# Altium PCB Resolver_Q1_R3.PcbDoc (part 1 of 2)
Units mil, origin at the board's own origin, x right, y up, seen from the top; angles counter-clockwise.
Board outline 2524 x 1600 mil, 2 copper layers (Top Layer, Bottom Layer), stack 62 mil thick; 100 components, 53 nets, 290 pads, 103 vias.
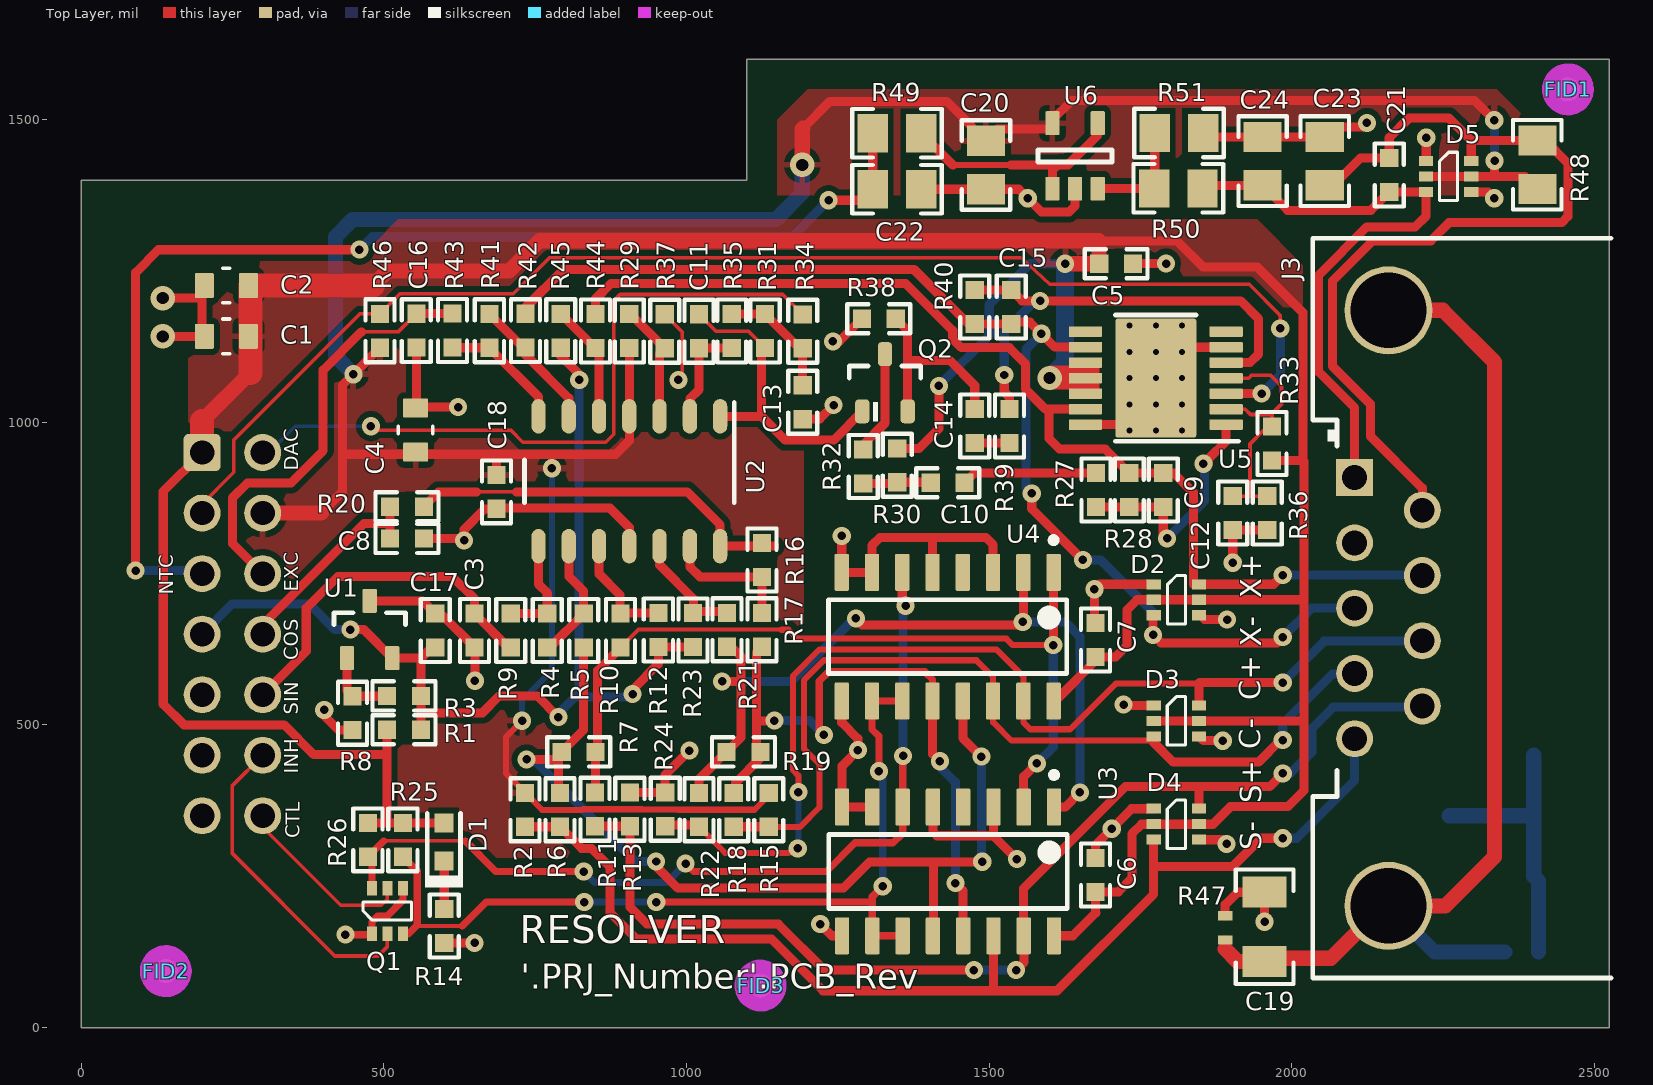
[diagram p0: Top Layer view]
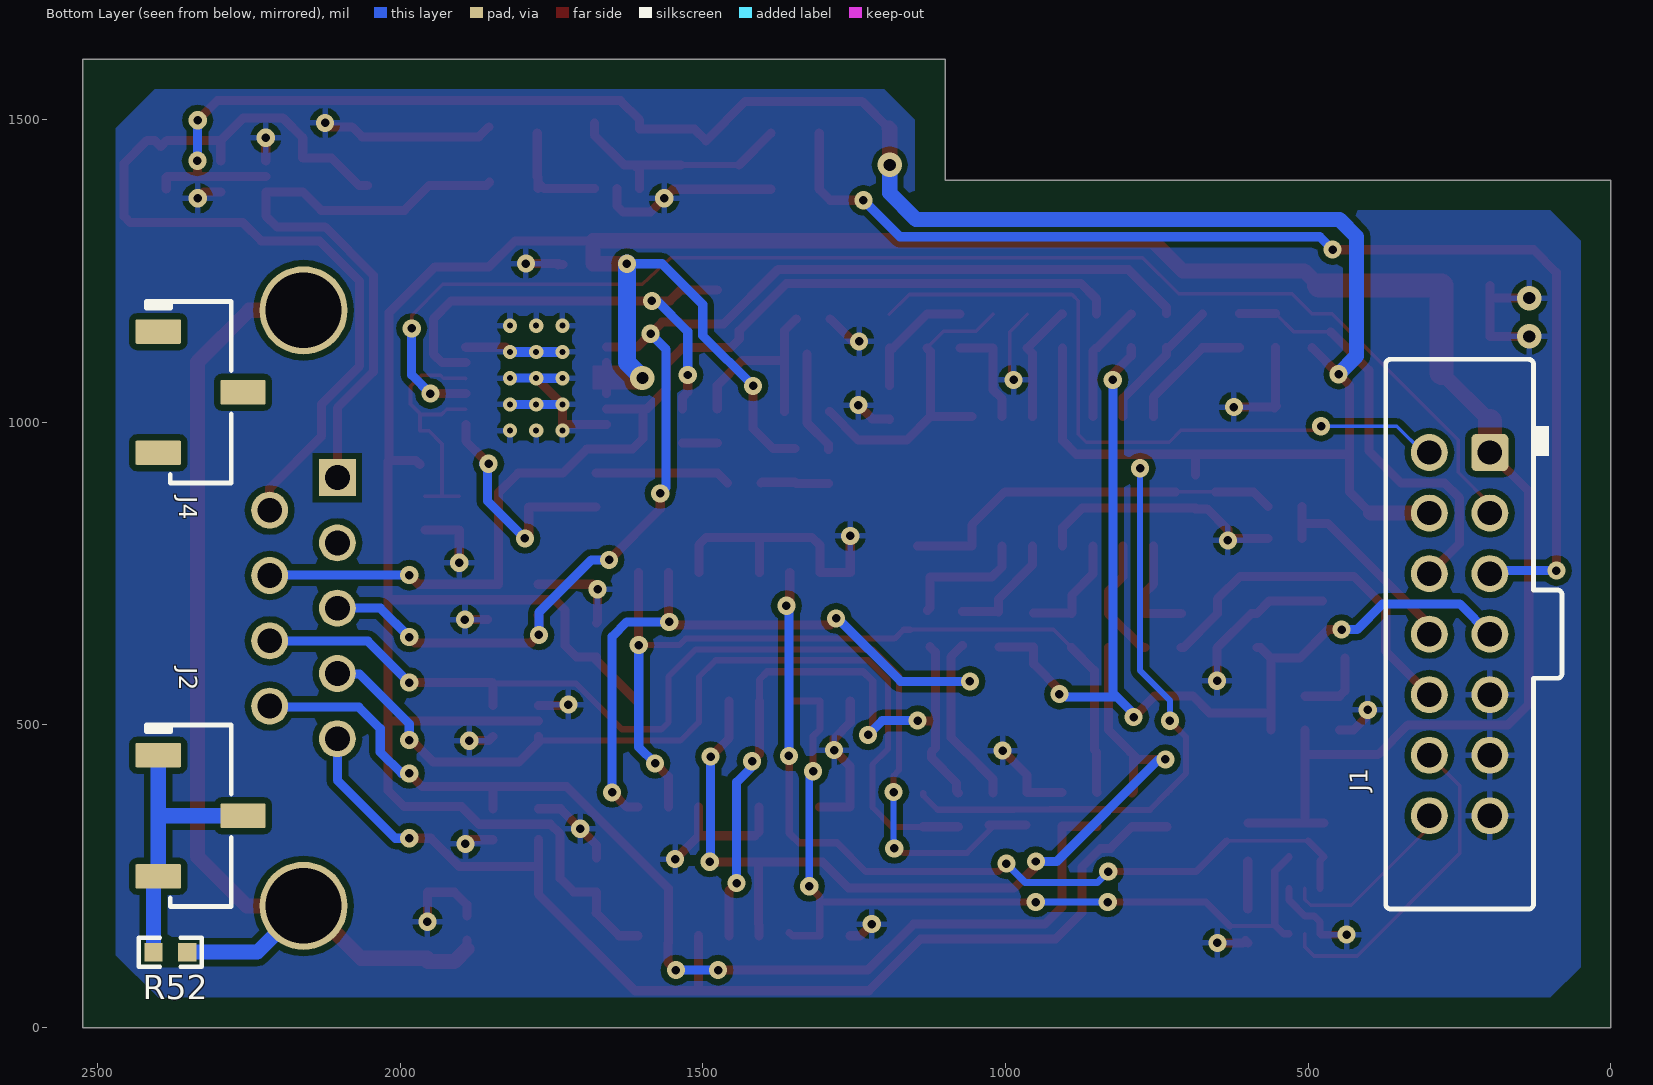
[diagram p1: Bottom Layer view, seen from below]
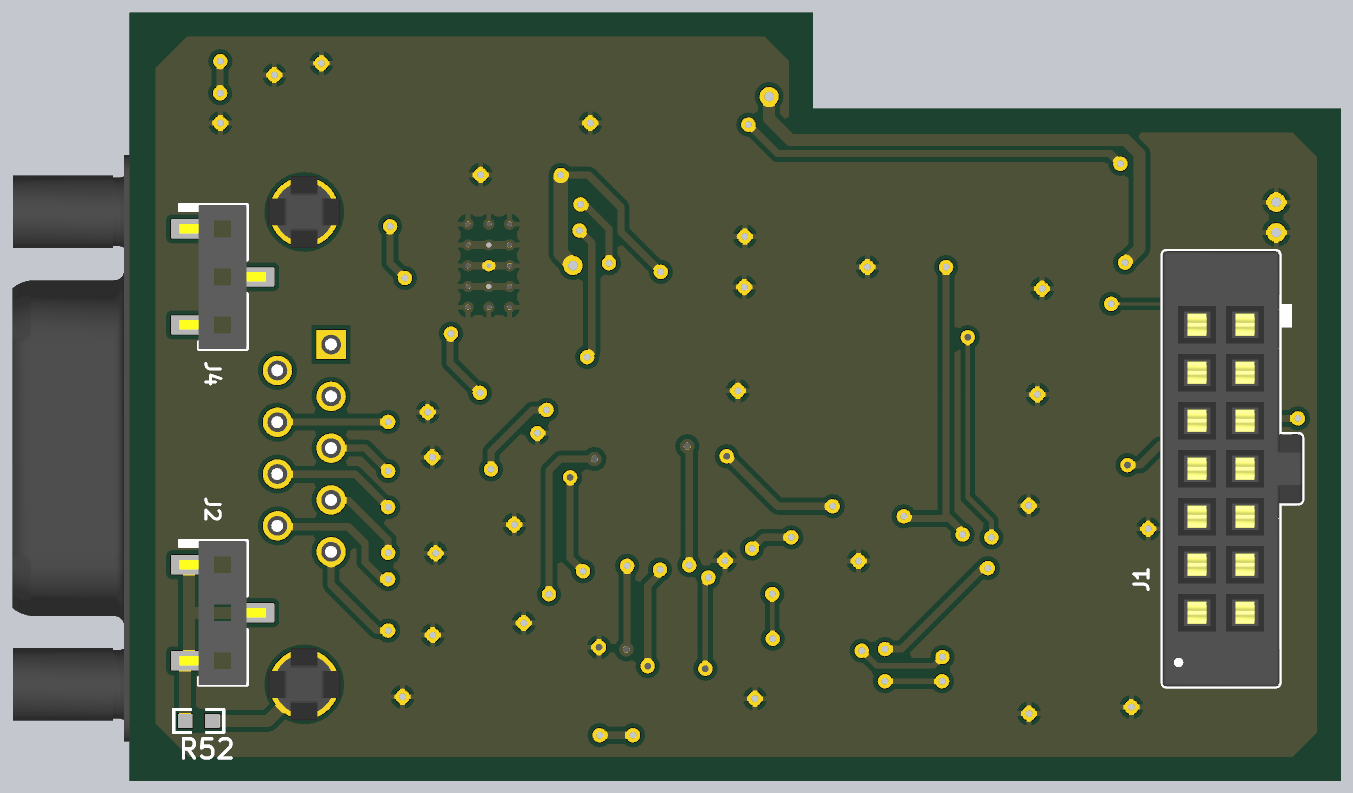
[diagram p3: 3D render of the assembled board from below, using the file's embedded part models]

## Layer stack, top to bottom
Top Solder: solder mask 0.4, Solder Resist, Dk 3.5
Top Layer: signal copper 1.4
Dielectric1: core 59.2, FR-4, Dk 4.8
Bottom Layer: signal copper 1.4
Bottom Solder: solder mask 0.4, Solder Resist, Dk 3.5

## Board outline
0,0 0,1400 1100,1400 1100,1600 2524,1600 2524,0

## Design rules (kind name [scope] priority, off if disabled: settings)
AcuteAngle [All] p1: minimum=4.50000000000000E+0001 checktracksonly=FALSE
AssemblyTestPointUsage [All] p1: valid=2
BoardOutlineClearance BoardOutlineClearance_MountingHoles [OnCopper and InComponentClass('Mounting Holes')] p1: gap=39.37 ignorepadtopadclearanceinfootprint=FALSE
BoardOutlineClearance BoardOutlineClearance_Poly [OnCopper and IsPoly] p2: gap=25 ignorepadtopadclearanceinfootprint=FALSE
BoardOutlineClearance [OnCopper and Not InComponentClass('Logo') and not InComponentClass('FiducialMark') and not InRegion(1000,500,4000,800) and not InPoly] p3: gap=50 ignorepadtopadclearanceinfootprint=FALSE
Clearance Clearance_Keepouts [((IsTrack Or IsArc) And Not InPoly) And IsFree and IsKeepOut vs ((IsTrack Or IsArc) And Not InPoly) And IsFree and IsKeepOut] p1: gap=0 ignorepadtopadclearanceinfootprint=FALSE
Clearance Clearance_Poly [InPolygon] p2: gap=10 ignorepadtopadclearanceinfootprint=TRUE
Clearance Clearance_FiducialMark [IsKeepOut and InComponentClass('FiducialMark') vs IsPad and InComponentClass('FiducialMark')] p3: gap=0 ignorepadtopadclearanceinfootprint=FALSE
Clearance [All] p4: gap=7.87 ignorepadtopadclearanceinfootprint=TRUE
ComponentClearance ComponentClearance_MountingHoles_FiducialMarks [InComponentClass('Mounting Holes') vs InComponentClass('FiducialMark')] p1: gap=50 collisioncheckmode=3 verticalgap=10 showdistances=FALSE
ComponentClearance ComponentClearance_Shunt [InComponentClass('Header') vs InComponentClass('Shunt')] p2: gap=0 collisioncheckmode=3 verticalgap=0 showdistances=FALSE
ComponentClearance ComponentClearance_Logo [InComponentClass('Logo')] p3: gap=20 collisioncheckmode=3 verticalgap=10 showdistances=FALSE
ComponentClearance ComponentClearance_ScrewToNut [(HasFootprint('NY PMS 440 0025 PH')) vs (HasFootprint('Keystone_1902C'))] p4: gap=5 collisioncheckmode=3 verticalgap=10 showdistances=FALSE
ComponentClearance ComponentClearance_MountingHoles [InComponentClass('Mounting Holes')] p5: gap=250 collisioncheckmode=3 verticalgap=100000 showdistances=FALSE
ComponentClearance ComponentClearance_SmallPassives [HasFootprint('0201*') or HasFootprint('0402*') or HasFootprint('0508') or HasFootprint('0603*') or HasFootprint('0612') or HasFootprint('0805*') or HasFootprint('0815*') or HasFootprint('0830*') or HasFootprint('1206*') or HasFootprint('1210*') or HasFootprint('1808*') or HasFootprint('1812*') or HasFootprint('1825*') or HasFootprint('2010*') or HasFootprint('2220*') or HasFootprint('2225*') or HasFootprint('2512*') or HasFootprint('2728*') or HasFootprint('3518*') vs HasFootprint('0201*') or HasFootprint('0402*') or HasFootprint('0508') or HasFootprint('0603*') or HasFootprint('0612') or HasFootprint('0805*') or HasFootprint('0815*') or HasFootprint('0830*') or HasFootprint('1206*') or HasFootprint('1210*') or HasFootprint('1808*') or HasFootprint('1812*') or HasFootprint('1825*') or HasFootprint('2010*') or HasFootprint('2220*') or HasFootprint('2225*') or HasFootprint('2512*') or HasFootprint('2728*') or HasFootprint('3518*')] p6: gap=14.96 collisioncheckmode=3 verticalgap=10 showdistances=FALSE
ComponentClearance ComponentClearance_THtoSMT [IsThruComponent vs IsSMTComponent] p7: gap=40 collisioncheckmode=3 verticalgap=30 showdistances=FALSE
ComponentClearance ComponentClearance_THtoTH [IsThruComponent vs IsThruComponent] p8: gap=30 collisioncheckmode=3 verticalgap=30 showdistances=FALSE
ComponentClearance [All] p9: gap=30 collisioncheckmode=3 verticalgap=10 showdistances=FALSE
DiffPairsRouting [All] p1: maxlimit=100 minlimit=10 mostfreqgap=10 toplayer_minwidth=15 toplayer_maxwidth=15 toplayer_prefwidth=15 bottomlayer_minwidth=15 bottomlayer_maxwidth=15 bottomlayer_prefwidth=15 maxuncoupledlength=1000
FabricationTestPointUsage TestPointUsage [All] p1: valid=2 allowmultiple=FALSE
FabricationTestpoint Testpoint [All] p1: side=3 testpointundercomponent=TRUE minsize=40 maxsize=100 preferedsize=60 minholesize=0 maxholesize=40 preferedholesize=32 testpointgrid=1 allowsidetop=TRUE allowsidebottom=TRUE usegrid=TRUE gridtolerance=0.01
FanoutControl Fanout_LCC [IsLCC] p1: bgadir=Out bgaviamode=Centered fanoutstyle=Auto fanoutdirection=Alternating viagrid=1 // Fanout_LCC (Default Rule)
FanoutControl Fanout_BGA [IsBGA] p2: bgadir=Out bgaviamode=Centered fanoutstyle=Auto fanoutdirection=Alternating viagrid=1 // Fanout_BGA (Default Rule)
FanoutControl Fanout_Default [All] p4: bgadir=Out bgaviamode=Centered fanoutstyle=Auto fanoutdirection=Alternating viagrid=1 // Fanout_Default (Default Rule)
FanoutControl Fanout_Small [(CompPinCount < 5)] p5: bgadir=Out bgaviamode=Centered fanoutstyle=Auto fanoutdirection=OutThenIn viagrid=1 // Fanout_Small (Default Rule)
HoleSize [All] p1: absolutevalues=TRUE maxlimit=251 minlimit=7.87 maxpercent=80.000 minpercent=20.000
MinimumAnnularRing MinimumAnnularRing_ThermalPadVias [IsVia and InAnyComponent] p1: minimumring=5.91
MinimumAnnularRing [All] p2: minimumring=7.87
MinimumSolderMaskSliver MinimumSolderMaskSliver_Logo [InComponentClass('Logo') vs InComponentClass('Logo')] p1: minsoldermaskwidth=0.7
MinimumSolderMaskSliver [All] p2: minsoldermaskwidth=3.94
PlaneConnect [All] p1: planeconnectstyle=Relief reliefexpansion=10 reliefentries=4 reliefconductorwidth=10 reliefairgap=10
PolygonConnect [All] p1: connectstyle=Relief reliefconductorwidth=10 reliefentries=4 polygonreliefangle="90 Angle" airgapwidth=10
RoutingVias ThermalPadVias [IsVia and InAnyComponent] p1: holewidth=7.87 width=19.68 viastyle="Through Hole" minholewidth=7.87 minwidth=19.68 maxholewidth=12.99 maxwidth=23.62
RoutingVias [All] p2: holewidth=16 width=34 viastyle="Through Hole" minholewidth=7.87 minwidth=26 maxholewidth=40 maxwidth=65
SilkToBoardRegionClearance [Not ((IsComment or IsDesignator) And (Hide <> 'False')) and not InRegion(1000,500,4000,800)] p1:
SilkToSilkClearance SilkToSilkClearance_Pb-FreeLogo [(HasFootprint('Pb-Free_Overlay_Medium') OR HasFootprint('Pb-Free_Overlay_Small')) vs (HasFootprint('Pb-Free_Overlay_Medium') OR HasFootprint('Pb-Free_Overlay_Small'))] p1: silktosilkclearance=0
SilkToSilkClearance [All] p2: silktosilkclearance=3.94
SilkToSolderMaskClearance SilkToComponentPadClearance [(IsPad or IsFill or IsRegion) and InAnycomponent] p1: minsilkscreentomaskgap=5 clearancetoexposedcopper=TRUE
SilkToSolderMaskClearance "Silk to Solder Mask Opening" [All] p2: minsilkscreentomaskgap=3.94 clearancetoexposedcopper=FALSE
SolderMaskExpansion [All] p1: expansion=1.97
UnRoutedNet [All] p1: checkbadconnections=TRUE
Width [All] p1: maxlimit=100 minlimit=6 preferedwidth=10 checkconnectedcopper=TRUE
14 further rules are at their usual default settings.

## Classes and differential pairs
component class Excitation_Amplifier: C9 C10 C11 C12 C13 C14 C15 C16 C20 C21 C22 C23 C24 D2 D3 D4 D5 FID1 FID2 FID3 Q2 R27 R28 R29 R30 R31 R32 R33 R34 R35 R36 R37 R38 R39 R40 R41 R42 R43 R44 R45 R48 R49 R50 R51 U2 U5 U6 ZZ1 ZZ2 ZZ3 ZZ4
component class Analog_Front-end_Q1: C1 C2 C3 C4 C5 C6 C7 C8 C17 C18 C19 D1 J1 J2 J3 J4 Q1 R1 R2 R3 R4 R5 R6 R7 R8 R9 R10 R11 R12 R13 R14 R15 R16 R17 R18 R19 R20 R21 R22 R23 R24 R25 R26 R46 R47 R52 U1 U3 U4
component class FiducialMark: FID1 FID2 FID3
component class AssemblyNote: ZZ1 ZZ2 ZZ3 ZZ4

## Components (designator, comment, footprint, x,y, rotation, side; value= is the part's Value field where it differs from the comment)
C1 "CGA4J1X7S1E106K125AC" FP-CGA4J1X7S1E106K125AC_0805-MFG 240,1142.01 r180 top value=10µF
C2 "CGA4J1X7S1E106K125AC" FP-CGA4J1X7S1E106K125AC_0805-MFG 240,1225.78 r180 top value=10µF
C3 "GRM1885C1H150JA01D" 0603_HV 650,655.97 r90 top value=15pF
C4 "CGA4J1X7S1E106K125AC" FP-CGA4J1X7S1E106K125AC_0805-MFG 552.64,987.14 r90 top value=10µF
C5 "GRM188R71E104KA01D" 0603_HV 1709.81,1261.91 r180 top value=0.1uF
C6 "GRM188R71E104KA01D" 0603_HV 1675.88,252.28 r270 top value=0.1uF
C7 "GRM188R71E104KA01D" 0603_HV 1675.88,640.47 r270 top value=0.1uF
C8 "GRM1885C1H150JA01D" 0603_HV 538.3,808.1 r180 top value=15pF
C9 "GRM1885C1H180JA01D" 0603_HV 1787.65,888.05 r90 top value=18pF
C10 "GRM188R71H103KA01D" 0603_HV 1431.57,900 r0 top value=0.01uF
C11 "GRM1885C1H102JA01D" 0603_HV 1020.74,1150.36 r90 top value=1000pF
C12 "GRM188R71H103KA01D" 0603_HV 1902.5,850 r90 top value=0.01uF
C13 "GRM188R71H472KA01D" 0603_HV 1192.03,1033.04 r90 top value=4700pF
C14 "GRM188R71H103KA01D" 0603_HV 1476.23,993.72 r270 top value=0.01uF
C15 "GRM1885C1H180JA01D" 0603_HV 1536.47,1190.5 r270 top value=18pF
C16 "GRM1885C1H150JA01D" 0603_HV 553.84,1151.4 r90 top value=15pF
C17 "C1608X6S1C475K080AC" 0603_HV 585,655.97 r90 top value=4.7uF
C18 "GRM188R71E104KA01D" 0603_HV 686.19,885.06 r90 top value=0.1uF
C19 "12061C103JAT2A" 1206 1955,166.63 r90 top value=0.01uF
C20 "GRM219R71C104KA01D" 0805_HV 1494.74,1425 r270 top value=0.1uF
C21 "GRM188R71E104KA01D" 0603_HV 2161,1408.46 r90 top value=0.1uF
C22 "08051C103JAT2A" 0805_HV 1347.8,1385 r0 top value=0.01uF
C23 "08051C103JAT2A" 0805_HV 2054.45,1431.34 r90 top value=0.01uF
C24 "08051C103JAT2A" 0805_HV 1951.81,1431.34 r90 top value=0.01uF
D1 "150060GS75000" WL-SMCW_GREEN 599.26,306.69 r90 top value=Green
D2 "BAS40DW-04-TP" SOT-363 1809.45,706.83 r0 top value=40V
D3 "BAS40DW-04-TP" SOT-363 1809.27,506.83 r0 top value=40V
D4 "BAS40DW-04-TP" SOT-363 1809.27,336.02 r0 top value=40V
D5 "BAS40DW-04-TP" SOT-363 2259.05,1406.05 r0 top value=40V
FID1 "Fiducial" Fiducial10-20 2456.15,1550 r0 top
FID2 "Fiducial" Fiducial10-20 140,93.32 r0 top
FID3 "Fiducial" Fiducial10-20 1122.36,69.51 r0 top
J1 "SFH11-PBPC-D07-ST-BK" Sullins_SFH11-xxxC-D07-ST-BK 250,650 r270 bottom
J2 "SSM-103-S-SV" Samtec_SSM-103-x-SV 2329.71,350 r270 bottom
J3 "5747840-5" TE_5747840-5 2535.07,692.94 r0 top
J4 "SSM-103-S-SV" Samtec_SSM-103-x-SV 2329.71,1049.66 r270 bottom
Q1 "DDC114YU-7-F" SOT-363 506.04,192.62 r90 top value="50 V"
Q2 "BC817-25,215" SOT-23 1328,1065.32 r90 top value="45 V"
R1 "RC0603FR-0710KL" 0603_HV 533.5,492.04 r180 top value=10.0k
R2 "RC0603FR-07100KL" 0603_HV 733.43,359.81 r90 top value=100k
R3 "RC0603FR-071K3L" 0603_HV 533.5,548.04 r0 top value=1.30k
R4 "RC0603FR-0715KL" 0603_HV 770.04,655.97 r90 top value=15.0k
R5 "RC0603FR-0732K4L" 0603_HV 830.31,655.97 r90 top value=32.4k
R6 "RC0603JR-070RL" 0603_HV 791.26,359.81 r90 top value=0
R7 "RC0603FR-07100KL" 0603_HV 822,455.54 r180 top value=100k
R8 "RC0603FR-076K2L" 0603_HV 448.54,519.42 r90 top value=6.20k
R9 "RC0603FR-0710RL" 0603_HV 709.81,655.97 r270 top value=10.0
R10 "RC0603FR-0732K4L" 0603_HV 891.26,655.97 r90 top value=32.4k
R11 "RC0603JR-070RL" 0603_HV 849.01,360.67 r90 top value=0
R12 "RC0603FR-0715KL" 0603_HV 953.62,657.04 r90 top value=15.0k
R13 "RC0603FR-0762KL" 0603_HV 906.57,360.67 r270 top value=62.0k
R14 "RC0603FR-0710KL" 0603_HV 600,168 r90 top value=10.0k
R15 "RC0603FR-07100KL" 0603_HV 1136.03,359.81 r90 top value=100k
R16 "RC0603FR-0715KL" 0603_HV 1125,772.54 r90 top value=15.0k
R17 "RC0603FR-0732K4L" 0603_HV 1125,657.15 r90 top value=32.4k
R18 "RC0603JR-070RL" 0603_HV 1078.23,359.81 r90 top value=0
R19 "RC0603FR-07100KL" 0603_HV 1094.36,455.54 r0 top value=100k
R20 "RC0603FR-0710RL" 0603_HV 538.3,860.57 r180 top value=10.0
R21 "RC0603FR-0732K4L" 0603_HV 1066.9,657.15 r90 top value=32.4k
R22 "RC0603JR-070RL" 0603_HV 1020.74,359.81 r90 top value=0
R23 "RC0603FR-0715KL" 0603_HV 1010.73,657.04 r90 top value=15.0k
R24 "RC0603FR-0762KL" 0603_HV 964.93,360.67 r270 top value=62.0k
R25 "RC0603FR-072K2L" 0603_HV 531.63,310.19 r90 top value=2.20k
R26 "RC0603FR-072K2L" 0603_HV 473.82,310.19 r90 top value=2.20k
R27 "RT0603BRD0749K9L" 0603_HV 1676.45,888.05 r270 top value=49.9k
R28 "RC0603FR-07470KL" 0603_HV 1731.45,888.05 r90 top value=470k
R29 "RC0603FR-073KL" 0603_HV 905.68,1150.65 r270 top value=3.00k
R30 "RC0603FR-0710KL" 0603_HV 1348.22,928.93 r90 top value=10.0k
R31 "RC0603FR-073K9L" 0603_HV 1130,1150.65 r90 top value=3.90k
R32 "RC0603FR-0720RL" 0603_HV 1292.22,927.01 r270 top value=20.0
R33 "RC0603FR-0710KL" 0603_HV 1967.3,965 r270 top value=10.0k
R34 "RC0603FR-073K9L" 0603_HV 1192.03,1150.24 r90 top value=3.90k
R35 "RC0603FR-0715KL" 0603_HV 1075,1150.65 r90 top value=15.0k
R36 "RC0603FR-0710KL" 0603_HV 1959.36,850 r90 top value=10.0k
R37 "RC0603FR-073KL" 0603_HV 964.2,1150.36 r270 top value=3.00k
R38 "RC0603FR-0710KL" 0603_HV 1317.76,1170.93 r0 top value=10.0k
R39 "RT0603BRD0749K9L" 0603_HV 1533.62,993.72 r90 top value=49.9k
R40 "RC0603FR-07470KL" 0603_HV 1476.23,1190.5 r270 top value=470k
R41 "RC0603FR-0710KL" 0603_HV 674.47,1151.11 r270 top value=10.0k
R42 "RC0603FR-0763K4L" 0603_HV 734.21,1151.4 r270 top value=63.4k
R43 "RC0603FR-0710RL" 0603_HV 613.65,1151.69 r90 top value=10.0
R44 "RC0603FR-0763K4L" 0603_HV 849.84,1150.94 r270 top value=63.4k
R45 "RC0603FR-0710KL" 0603_HV 792.42,1151.11 r90 top value=10.0k
R46 "RC0603FR-0710KL" 0603_HV 493.74,1151.11 r270 top value=10.0k
R47 "ERJ-2RKF1004X" 0402S 1890,164.8 r270 top value=1.00Meg
R48 "ERJ-6ENF1001V" 0805_HV 2405.58,1425.41 r270 top value=1.00k
R49 "CRCW0805100RDHEAP" 0805_HV 1347.8,1477.46 r180 top value=100
R50 "CRCW0805100RDHEAP" 0805_HV 1812.64,1386.46 r180 top value=100
R51 "ERJ-6ENF2002V" 0805_HV 1813.57,1477.92 r180 top value=20.0k
R52 "RC0603JR-070RL" 0603_HV 2379.71,124.67 r180 bottom value=0
U1 "TLV431BQDBZRQ1" DBZ0003A_N 476.79,657.65 r90 top
U2 "OPA4171AQDRQ1" D0014A_L 905.68,902.57 r270 top
U3 "CD4053BQM96Q1" D0016A-MFG 1432.14,258.05 r270 top
U4 "CD4053BQM96Q1" D0016A-MFG 1431.57,645.84 r270 top
U5 "ALM2402FQPWPRQ1" PWP0014H_N 1775.31,1072.89 r180 top
U6 "TLV6001IDBVR" DBV0005A_N 1641.97,1440 r90 top
ZZ1 "This Assembly Note is for PCB labels only" AssemblyNoteLabel 78.26,2238 r0 top
ZZ2 "These assemblies are ESD sensitive, ESD precautions shall be observed." AssemblyNote 78.26,2129.11 r0 top
ZZ3 "These assemblies must be clean and free from flux and all contaminants. Use of no clean flux is not acceptable." AssemblyNote 78.26,2040.56 r0 top
ZZ4 "These assemblies must comply with workmanship standards IPC-A-610 Class 2, unless otherwise specified." AssemblyNote 78.26,1952 r0 top

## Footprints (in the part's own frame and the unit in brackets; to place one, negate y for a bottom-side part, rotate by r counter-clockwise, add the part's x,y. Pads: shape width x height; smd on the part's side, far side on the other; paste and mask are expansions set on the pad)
0402S [mil] "Based on C0402S footprint from PADS legacy"
  rect 15x24 smd: 1(-20,0) 2(20,0)
  body extent -22,-12 22,12, height 24
0603_HV [mil] "Ernesto recommended land pattern.  26 mil between pads."
  rect 30x30 smd: 1(-28,0) 2(28,0)
  silkscreen extent -52,-24 52,24, body extent -34,-19 34,19, height 39
0805_HV [mil] "0805 with 30mil clearance between pads"
  rect 50x63 smd: 1(-40,0) 2(40,0)
  silkscreen extent -74,-40 74,40, body extent -43,-29 43,29, height 57
1206 [mm] "1206 from SM-752 data"
  rect 1.3x1.85 smd: 1(-1.45,0) 2(1.45,0)
  silkscreen extent -2.4,-1.21 2.4,1.21, body extent -1.7,-0.9 1.7,0.9, height 1.35
AssemblyNote [mil] "Assembly Note"
AssemblyNoteLabel [mil] "Assembly Note for PCB Labels"
D0014A_L [mm] "SOIC, 14-Leads, Body 8.7x3.9mm, Pitch 1.27mm, IPC High Density"
  oval 1.45x0.6 smd: 1(-2.725,3.81) 2(-2.725,2.54) 3(-2.725,1.27) 4(-2.725,0) 5(-2.725,-1.27) 6(-2.725,-2.54) 7(-2.725,-3.81) 8(2.725,-3.81) 9(2.725,-2.54) 10(2.725,-1.27) 11(2.725,0) 12(2.725,1.27) 13(2.725,2.54) 14(2.725,3.81)
  silkscreen extent -3.3,-4.4 0.9,4.4, body extent -3.02,-4.32 3.02,4.32, height 1.6
D0016A-MFG [mm] "SOP, 16-Leads, Body 5.1x4.5mm, Pitch 0.65mm, IPC High Density"
  rrect17% 1.55x0.6 smd paste-1000 mask+0: 1(-2.7,4.445) 2(-2.7,3.175) 3(-2.7,1.905) 4(-2.7,0.635) 5(-2.7,-0.635) 6(-2.7,-1.905) 7(-2.7,-3.175) 8(-2.7,-4.445) 9(2.7,-4.445) 10(2.7,-3.175) 11(2.7,-1.905) 12(2.7,-0.635) 13(2.7,0.635) 14(2.7,1.905) 15(2.7,3.175) 16(2.7,4.445)
  silkscreen extent -4.17,-5 1.55,5, body extent -3.57,-5.25 3.57,5.25, height 0.25
DBV0005A_N [mm] "SOT23, 5-Leads, Body 2.9x1.6mm, Pitch 0.95mm, Lead Span 2.8mm, IPC Medium Density"
  rrect17% 1x0.6 smd: 1(-1.375,0.95) 2(-1.375,0) 3(-1.375,-0.95) 4(1.375,-0.95) 5(1.375,0.95)
  silkscreen extent -0.25,-1.55 0.25,1.55, body extent -1.42,-1.46 1.42,1.46, height 1.09
DBZ0003A_N [mm] "SOT23, 3-Leads, Body 2.9x1.3mm, Pitch 0.95mm, Lead Span 2.4mm, IPC Medium Density"
  rrect17% 1x0.6 smd: 1(-1.2,0.95) 2(-1.2,-0.95) 3(1.2,0)
  silkscreen extent 0.2,-1.5 0.7,1.5, body extent -1.26,-1.46 1.26,1.46, height 0.98
Fiducial10-20 [mm]
  round 1 smd mask+0.5: 1(0,0)
  Top Layer keep-out circle w1.178: c0,0 r0.5
FP-CGA4J1X7S1E106K125AC_0805-MFG [mm]
  rrect13% 0.8x1.05 smd paste+0 mask+0: 1(-0.925,0) 2(0.925,0)
  silkscreen extent -0.15,-0.72 0.15,0.72, body extent -1.43,-0.82 1.43,0.82, height 0.25
PWP0014H_N [mm] "HTSSOP-14"
  rrect22% 1.4x0.45 smd: 1(-2.95,1.95) 2(-2.95,1.3) 3(-2.95,0.65) 4(-2.95,0) 5(-2.95,-0.65) 6(-2.95,-1.3) 7(-2.95,-1.95) 8(2.95,-1.95) 9(2.95,-1.3) 10(2.95,-0.65) 11(2.95,0) 12(2.95,0.65) 13(2.95,1.3) 14(2.95,1.95)
  rrect6% 3.4x5 smd paste-2 mask-2: 15(0,0)
  silkscreen extent -3.47,-2.65 1.7,2.65, body extent -3.21,-2.5 3.21,2.5, height 1
Samtec_SSM-103-x-SV [mm] "Receptacle, 2.54mm, 3x1, SMT"
  rrect10% 1.02x1.905 smd: 1(-2.54,-1.777) 2(0,1.777) 3(2.54,-1.777)
  silkscreen extent -3.81,-2.27 3.81,1.28, body extent -3.81,-2.29 3.81,2.29, height 7.51
SOT-23 [mm] "SOT23, 3-Leads, Body 2.9x1.3mm, Pitch 0.95mm, Lead Span 2.5mm, IPC Medium Density"
  rrect50% 1x0.6 smd: 1(-1.2,0.95) 2(-1.2,-0.95) 3(1.2,0)
  silkscreen extent -1.63,-1.5 0.7,1.5, body extent -1.16,-1.45 1.21,1.45, height 1
SOT-363 [mm]
  rect 0.6x0.42 smd mask+0.051: 1(-0.95,0.65) 2(-0.95,0) 3(-0.95,-0.65) 4(0.95,-0.65) 5(0.95,0) 6(0.95,0.65)
  silkscreen extent -0.38,-1.02 0.38,1.02, body extent -1.1,-1.1 1.1,1.1, height 1.12
Sullins_SFH11-xxxC-D07-ST-BK [mm] "Receptacle, 2.54mm, 7x2, TH"
  rrect25% 1.55x1.55 hole 1.02: 1(-7.62,1.27)
  round 1.55 hole 1.02: 2(-7.62,-1.27) 3(-5.08,1.27) 4(-5.08,-1.27) 5(-2.54,1.27) 6(-2.54,-1.27) 7(0,1.27) 8(0,-1.27) 9(2.54,1.27) 10(2.54,-1.27) 11(5.08,1.27) 12(5.08,-1.27) 13(7.62,1.27) 14(7.62,-1.27)
  silkscreen extent -11.53,-3.1 11.53,4.3, body extent -11.53,-3.1 11.53,4.3, height 8.71
TE_5747840-5 [mm] "D-Sub, 2.74mm, 9 Position, R/A, TH"
  rect 1.55x1.55 hole 1.04: 1(-10.954,5.48)
  round 1.55 hole 1.04: 2(-10.954,2.74) 3(-10.954,0) 4(-10.954,-2.74) 5(-10.954,-5.48) 6(-8.114,4.11) 7(-8.114,1.37) 8(-8.114,-1.37) 9(-8.114,-4.11)
  round 3.7 hole 3.17: 10(-9.534,12.495) 11(-9.534,-12.495)
  silkscreen extent -12.71,-15.52 -0.2,15.52, body extent -12.71,-15.52 5.89,15.52, height 12.55
WL-SMCW_GREEN [mm] "WURTH"
  rect 0.8x0.8 smd: 1(-0.8,0) 2(0.8,0)
  silkscreen extent -1.9,-0.8 1.2,0.8, body extent -0.85,-0.45 0.85,0.45, height 0.8

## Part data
C1 C2 C4: library part CMP-0091069-1, "Cap Ceramic 10uF 25V X7S 10% Pad SMD 0805 +125°C Automotive T/R", Manufacturer="TDK Corporation", Operating Temperature Range="-55°C to +125°C", TempCo=22%, Temperature Characteristic=X7S, Tolerance_%=0.1%, ValueDisplayed=10uF
C3 C8 C16: library part CMP-0007184-4, "CAP, CERM, 15 pF, 50 V, +/- 5%, C0G/NP0, 0603", Cap_Case=0603, Manufacturer=MuRata, Supplier Part Number 1=490-1407-1-ND, TempCo=C0G/NP0, Tolerance_%=5%, Value1=Unknown, Value2=50V, ValueDisplayed=15pF
C5 C6 C7 C18 C21: library part CMP-0007404-4, "CAP, CERM, 0.1 uF, 25 V, +/- 10%, X7R, 0603", Cap_Case=0603, Manufacturer=MuRata, Supplier Part Number 1=490-1524-1-ND, TempCo=X7R, Tolerance_%=10%, Value1=Unknown, Value2=25V, ValueDisplayed=0.1uF
C9 C15: library part CMP-0007190-4, "CAP, CERM, 18 pF, 50 V, +/- 5%, C0G/NP0, 0603", Cap_Case=0603, Manufacturer=MuRata, Supplier Part Number 1=490-1409-1-ND, TempCo=C0G/NP0, Tolerance_%=5%, Value1=Unknown, Value2=50V, ValueDisplayed=18pF
C10 C12 C14: library part CMP-0007433-4, "CAP, CERM, 0.01 uF, 50 V, +/- 10%, X7R, 0603", Cap_Case=0603, Manufacturer=MuRata, Supplier Part Number 1=490-1512-1-ND, TempCo=X7R, Tolerance_%=10%, Value1=Unknown, Value2=50V, ValueDisplayed=0.01uF
C11: library part CMP-0007173-4, "CAP, CERM, 1000 pF, 50 V, +/- 5%, C0G/NP0, 0603", Cap_Case=0603, Manufacturer=MuRata, Supplier Part Number 1=490-1451-1-ND, TempCo=C0G/NP0, Tolerance_%=5%, Value1=Unknown, Value2=50V, ValueDisplayed=1000pF
C13: library part CMP-0007456-4, "CAP, CERM, 4700 pF, 50 V, +/- 10%, X7R, 0603", Cap_Case=0603, Manufacturer=MuRata, Supplier Part Number 1=490-1506-1-ND, TempCo=X7R, Tolerance_%=10%, Value1=Unknown, Value2=50V, ValueDisplayed=4700pF
C17: library part CMP-0007028-3, "CAP, CERM, 4.7 uF, 16 V, +/- 10%, X6S, 0603", Cap_Case=0603, Manufacturer=TDK, Supplier Part Number 1=445-9118-1-ND, TempCo=X6S, Tolerance_%=10%, Value1="0.003728 ohm", Value2=16V, ValueDisplayed=4.7uF
C19: library part CMP-0008484-2, "CAP, CERM, 0.01 uF, 100 V, +/- 5%, X7R, 1206", Cap_Case=1206, Manufacturer=AVX, Supplier Part Number 1=478-3783-1-ND, TempCo=X7R, Tolerance_%=5%, Value1="0.119 ohm", Value2=100V, ValueDisplayed=0.01uF
C20: library part CMP-0008209-1, "CAP, CERM, 0.1 uF, 16 V, +/- 10%, X7R, 0805", Cap_Case=0805, Manufacturer=MuRata, Supplier Part Number 1=490-1683-1-ND, TempCo=X7R, Tolerance_%=10%, Value1=Unknown, Value2=16V, ValueDisplayed=0.1uF
C22 C23 C24: library part CMP-0007542-1, "CAP, CERM, 0.01 uF, 100 V, +/- 5%, X7R, 0805", Cap_Case=0805, Manufacturer=AVX, Supplier Part Number 1=478-3745-1-ND, TempCo=X7R, Tolerance_%=5%, Value1="0.078 ohm", Value2=100V, ValueDisplayed=0.01uF
D1: library part CMP-0002905-2, "LED, Green, SMD", Color=Green, Manufacturer="Wurth Elektronik", Value1=W, Value2=3.2V
D2 D3 D4 D5: library part CMP-0028604-2, "Diode, Schottky, 40 V, 0.2 A, SOT-363", Manufacturer="Micro Commercial Components", Value1=0.2A, Value2=1V
FID1 FID2 FID3: library part CMP-0077181-1, "Fiducial mark.  There is nothing to buy or mount.", Manufacturer=N/A
J1: library part CMP-0054668-1, "Receptacle, 2.54mm, 7x2, Gold, Black, TH", Color=Black, Current_A=3A, Manufacturer="Sullins Connector Solutions", Supplier Part Number 1=S9195-ND, Voltage_V=1kV
J2 J4: library part CMP-0078183-1, "Receptacle, 2.54mm, 3x1, Gold with Tin tail, SMT", Color=Black, Current_A=5.2A, Manufacturer=Samtec, Supplier Part Number 1=SAM1152-03-ND, Voltage_V=405V
J3: library part CMP-0054938-2, "D-Sub, 2.74mm, 9 Position, R/A, TH", Color=Black, Manufacturer="TE Connectivity", Supplier Part Number 1=A32093-ND
Q1: library part CMP-0000496-2, "Transistor, Dual NPN, 50 V, 0.1 A, SOT-363", Manufacturer=Panasonic, Supplier Part Number 1=DMC564040RCT-ND, Value1="0.1 A"
Q2: library part CMP-0000480-2, "Transistor, NPN, 45 V, 0.5 A, SOT-23", Manufacturer="NXP Semiconductor", Supplier Part Number 1=568-1630-1-ND, Value1="0.5 A", Value2=400
R1 R14 R30 R33 R36 R38 R41 R45 R46: library part CMP-0022746-5, "RES, 10.0 k, 1%, 0.1 W, 0603", Manufacturer=Yageo, Power_W=100mW, Supplier Part Number 1=311-10.0KHRCT-ND, TempCo="100 ppm/C", Tolerance_%=1%, Value2=0.1W, Value_Code=10k0, ValueDisplayed=10.0k
R2 R7 R15 R19: library part CMP-0022735-5, "RES, 100 k, 1%, 0.1 W, 0603", Manufacturer=Yageo, Power_W=100mW, Supplier Part Number 1=311-100KHRCT-ND, TempCo="100 ppm/C", Tolerance_%=1%, Value2=0.1W, Value_Code=100k
R3: library part CMP-0022877-5, "RES, 1.30 k, 1%, 0.1 W, 0603", Manufacturer=Yageo, Power_W=100mW, Supplier Part Number 1=311-1.30KHRCT-ND, TempCo="100 ppm/C", Tolerance_%=1%, Value2=0.1W, Value_Code=1k30, ValueDisplayed=1.30k
R4 R12 R16 R23 R35: library part CMP-0022816-5, "RES, 15.0 k, 1%, 0.1 W, 0603", Manufacturer=Yageo, Power_W=100mW, Supplier Part Number 1=311-15.0KHRCT-ND, TempCo="100 ppm/C", Tolerance_%=1%, Value2=0.1W, Value_Code=15k0, ValueDisplayed=15.0k
R5 R10 R17 R21: library part CMP-0023030-5, "RES, 32.4 k, 1%, 0.1 W, 0603", Manufacturer=Yageo, Power_W=100mW, Supplier Part Number 1=311-32.4KHRCT-ND, TempCo="100 ppm/C", Tolerance_%=1%, Value2=0.1W, Value_Code=32k4, ValueDisplayed=32.4k
R6 R11 R18 R22 R52: library part CMP-0025885-5, "RES, 0, 5%, 0.1 W, 0603", Manufacturer=Yageo, Power_W=100mW, Supplier Part Number 1=311-0.0GRCT-ND, TempCo="200 ppm/C", Tolerance_%=5%, Value2=0.1W, Value_Code=0000, ValueDisplayed=0
R8: library part CMP-0023248-5, "RES, 6.20 k, 1%, 0.1 W, 0603", Manufacturer=Yageo, Power_W=100mW, Supplier Part Number 1=311-6.20KHRCT-ND, TempCo="100 ppm/C", Tolerance_%=1%, Value2=0.1W, Value_Code=6k20, ValueDisplayed=6.20k
R9 R20 R43: library part CMP-0022751-4, "RES, 10.0, 1%, 0.1 W, 0603", Manufacturer=Yageo, Power_W=100mW, Supplier Part Number 1=311-10.0HRCT-ND, TempCo="100 ppm/C", Tolerance_%=1%, Value2=0.1W, Value_Code=10R0, ValueDisplayed=10.0
R13 R24: library part CMP-0023220-5, "RES, 62.0 k, 1%, 0.1 W, 0603", Manufacturer=Yageo, Power_W=100mW, Supplier Part Number 1=311-62.0KHRCT-ND, TempCo="100 ppm/C", Tolerance_%=1%, Value2=0.1W, Value_Code=62k0, ValueDisplayed=62.0k
R25 R26: library part CMP-0022986-5, "RES, 2.20 k, 1%, 0.1 W, 0603", Manufacturer=Yageo, Power_W=100mW, Supplier Part Number 1=311-2.20KHRCT-ND, TempCo="100 ppm/C", Tolerance_%=1%, Value2=0.1W, Value_Code=2k20, ValueDisplayed=2.20k
R27 R39: library part CMP-0024283-1, "RES, 49.9 k, 0.1%, 0.1 W, 0603", Manufacturer="Yageo America", Power_W=100mW, TempCo="25 ppm/C", Tolerance_%=0.1%, Value2=0.1W, Value_Code=49k9, ValueDisplayed=49.9k
R28 R40: library part CMP-0023128-4, "RES, 470 k, 1%, 0.1 W, 0603", Manufacturer=Yageo, Power_W=100mW, Supplier Part Number 1=311-470KHRCT-ND, TempCo="100 ppm/C", Tolerance_%=1%, Value2=0.1W, Value_Code=470k
R29 R37: library part CMP-0023091-5, "RES, 3.00 k, 1%, 0.1 W, 0603", Manufacturer=Yageo, Power_W=100mW, Supplier Part Number 1=311-3.00KHRCT-ND, TempCo="100 ppm/C", Tolerance_%=1%, Value2=0.1W, Value_Code=3k00, ValueDisplayed=3.00k
R31 R34: library part CMP-0023090-5, "RES, 3.90 k, 1%, 0.1 W, 0603", Manufacturer=Yageo, Power_W=100mW, Supplier Part Number 1=311-3.90KHRCT-ND, TempCo="100 ppm/C", Tolerance_%=1%, Value2=0.1W, Value_Code=3k90, ValueDisplayed=3.90k
R32: library part CMP-0022908-4, "RES, 20.0, 1%, 0.1 W, 0603", Manufacturer=Yageo, Power_W=100mW, Supplier Part Number 1=311-20.0HRCT-ND, TempCo="100 ppm/C", Tolerance_%=1%, Value2=0.1W, Value_Code=20R0, ValueDisplayed=20.0
R42 R44: library part CMP-0023224-5, "RES, 63.4 k, 1%, 0.1 W, 0603", Manufacturer=Yageo, Power_W=100mW, Supplier Part Number 1=311-63.4KHRCT-ND, TempCo="100 ppm/C", Tolerance_%=1%, Value2=0.1W, Value_Code=63k4, ValueDisplayed=63.4k
R47: library part CMP-0026660-1, "RES, 1.00 M, 1%, 0.1 W, 0402", Manufacturer=Panasonic, Power_W=100mW, Supplier Part Number 1=P1.00MLCT-ND, TempCo="100 ppm/C", Tolerance_%=1%, Value2=0.1W, Value_Code=1M00, ValueDisplayed=1.00M
R48: library part CMP-0021519-3, "RES, 1.00 k, 1%, 0.125 W, AEC-Q200 Grade 0, 0805", Manufacturer=Panasonic, Power_W=125mW, Supplier Part Number 1=P1.00KCCT-ND, TempCo="100 ppm/C", Tolerance_%=1%, Value2=0.125W, Value_Code=1k00, ValueDisplayed=1.00k
R49 R50: library part CMP-0065350-1, "RES, 100, .5%, .125 W, AEC-Q200 Grade 0, 0805", Manufacturer=Vishay-Dale, Power_W=125mW, Supplier Part Number 1=541-100AZCT-ND, TempCo="50 ppm/C", Tolerance_%=0.5%, Value1=.5%, Value2=.125W, Value_Code=100R, ValueDisplayed=100
R51: library part CMP-0021614-3, "RES, 20.0 k, 1%, 0.125 W, AEC-Q200 Grade 0, 0805", Manufacturer=Panasonic, Power_W=125mW, Supplier Part Number 1=P20.0KCCT-ND, TempCo="100 ppm/C", Tolerance_%=1%, Value2=0.125W, Value_Code=20k0, ValueDisplayed=20.0k
U1: library part CMP-0033032-1, "Automotive Catalog Low-Voltage Adjustable Precision Shunt Regulator, 15 mA, -40 to 125 degC, 3-pin SOT-23 (DBZ), Green (RoHS & no Sb/Br)", Manufacturer="Texas Instruments", Rating=Automotive
U2: library part CMP-0860035-1, "Automotive Catalog 36V, Low Power, RRO, General Purpose Operational Amplifier, D0014A (SOIC-14)", Alternate Manufacturer="Texas Instruments", Operating Temperature Range="-40 to 125 C", Rating=Automotive
U3 U4: library part CMP-0088292-1, "3 Circuit IC Switch 2:1 240Ohm 16-SOIC", Digikey Part Number=CD4053BQM96Q1-ND, Manufacturer="Texas Instruments", Max Supply Voltage=20V, Min Supply Voltage=3V, Mouser Part Number=595-CD4053BQM96Q1, Nominal Supply Current=0.04-0.08uA, On State Resistance=125O, Operating Temperature Range="-40°C to +125°C"
U5: library part CMP-0081971-2, "Dual Opamp with High Current Output, PWP0014H (HTSSOP-14)", Alternate Manufacturer="Texas Instruments"
U6: library part CMP-0073547-1, "1-MHz, Low-Power Operational Amplifier for Cost-Sensitive Systems, DBV0005A (SOT-23-5)", Alternate Manufacturer="Texas Instruments", Alternate PartNumber=TLV6001IDBVT
ZZ1: library part CMP-0003616-3
ZZ2: library part CMP-0077236-1
ZZ3: library part CMP-0077237-1
ZZ4: library part CMP-0077238-1

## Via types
v1: diameter 30, hole 14, Top Layer to Bottom Layer, 80 vias
v2: diameter 23.5, hole 10, Top Layer to Bottom Layer, tented both sides, 12 vias
v3: diameter 40, hole 20, Top Layer to Bottom Layer, 4 vias
v4: diameter 30, hole 14, Top Layer to Bottom Layer, tented both sides, 3 vias
v5: diameter 23.5, hole 10, Top Layer to Bottom Layer, 3 vias
v6: diameter 30, hole 14, Top Layer to Bottom Layer, tented top, 1 vias

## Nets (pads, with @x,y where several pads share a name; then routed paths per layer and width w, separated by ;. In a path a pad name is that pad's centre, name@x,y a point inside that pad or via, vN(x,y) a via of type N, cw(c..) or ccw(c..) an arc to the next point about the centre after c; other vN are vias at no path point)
COS+: D3.6 J3.8 R22.1 R24.2 U4.15 | length 1778.2
  Top Layer w6: 1168.62,288.54 1176.42,288.54 v1(1183.87,295.99)
  Top Layer w10: R22.1@1020.74,331.81 1064.01,288.54 1168.62,288.54 ; v1(1185,389.2) 1185,416.39 1176.13,425.27 1176.13,581.13 1219.76,624.77 1512.01,624.77 1556.57,580.2 U4.15@1556.57,539.54 1556.57,504.43 1568.08,492.92 1633.92,492.92 1709.67,568.67 1846.67,568.67
  Top Layer w15: R24.2@966.72,334.46 1026.59,334.46 R22.1@1026.93,334.81 ; D3.6@1846.67,532.42 1846.67,568.67 1848,570 v1(1985,570)
  Bottom Layer w10: v1(1183.87,295.99) 1183.87,308.36 1185,309.48 v1(1185,389.2)
  Bottom Layer w15: v1(1985,570) 2053.42,638.42 J3.8@2206.96,638.42
COS-: D3.3 J3.4 R15.1 R18.1 U4.14 | length 1491.6
  Top Layer w10: R15.1@1136.03,331.81 1187.81,331.81 1219.76,363.76 1219.76,434.79 1194,460.55 1194,573.73 1227.17,606.9 1478.91,606.9 1506.57,579.23 U4.14@1506.57,539.54 1506.57,504.46 1537.04,474 1764.63,474 D3.3@1771.87,481.24
  Top Layer w15: R18.1@1078.23,331.81 R15.1@1136.03,331.81 ; D3.3@1771.87,481.24 1771.87,471.07 1804.2,438.74 1945,438.74 1981.16,474.89 v1(1985,474.89)
  Bottom Layer w15: v1(1985,474.89) 1985,501.83 2067.06,583.89 J3.4@2095.14,583.89
CTRL: J1.14 Q1.5 | length 300.2
  Top Layer w6: J1.14@300,350 300,331.21 429.07,202.14 495.94,202.14 506.04,212.24 Q1.5@506.04,230.02
CTRL_CMOS: Q1.3 R25.1 U3.10 U3.11 U4.10 U4.11 | length 1424
  Top Layer w6: 553.81,168 629.7,168
  Top Layer w12: Q1.3@531.63,155.22 541.03,155.22 553.81,168 ; R25.1@531.63,282.19 555.27,258.55 555.27,169.46 ; 629.7,168 669.14,207.45 v1(831.14,207.45) ; v1(950.19,207.45) 1307.14,207.45 ; v1(1317.97,423.55) 1317.97,481.18 1306.57,492.58 U4.10@1306.57,539.54 U4.11@1356.57,539.54 ; v1(1324.28,233.56) 1307.14,216.42 1307.14,207.45 ; U3.11@1357.14,156.87 1352.02,151.75 U3.10@1307.14,151.75 1307.14,207.45
  Bottom Layer w12: v1(831.14,207.45) v1(950.19,207.45) ; v1(1317.97,423.55) 1324.28,417.24 v1(1324.28,233.56)
EXC+: C9.2 D2.6 J3.7 R28.2 R44.1 U5.13 | length 1808.7
  Top Layer w15: R44.1@849.84,1178.94 849.84,1203.59 875.79,1229.54 1361.74,1229.54 1440,1151.28 1440,1137.47 1454.22,1123.25 1533.22,1123.25 1560.09,1096.38 1560.09,1054.75 1593.13,1021.71 U5.13@1659.17,1021.71 ; 1599.06,1015.78 1599.06,973.07 1616.48,955.65 1691.86,955.65 R28.2@1731.45,916.05 C9.2@1787.65,916.05 1805.28,916.05 1837.31,884.02 1837.31,732.42 D2.6@1846.85,732.42 1969.81,732.42 v1(1985,747.61)
  Bottom Layer w15: v1(1985,747.61) 1985.14,747.47 J3.7@2206.96,747.47
EXC-: C15.2 D2.3 J3.3 R40.2 R42.1 U5.9 | length 2015.3
  Top Layer w15: R42.1@734.21,1179.4 734.21,1189.55 797.07,1252.42 1375.96,1252.42 1465.87,1162.5 R40.2@1476.23,1162.5 C15.2@1536.47,1162.5 1539.32,1165.35 1567.27,1165.35 v1(1586.5,1146.13) 1608.55,1124.07 U5.9@1659.17,1124.07 ; v1(1570.44,882.55) 1570.44,857.1 v1(1655,772.54) ; D2.3@1772.04,681.24 1770.76,679.95 v1(1770.76,648.74) 1783.99,635.5 1975.23,635.5 v1(1985,645.27)
  Bottom Layer w15: v1(1570.44,882.55) 1560.98,892.02 1560.98,1120.61 v1(1586.5,1146.13) ; v1(1655,772.54) 1684.08,772.54 1770.76,685.86 v1(1770.76,648.74) ; v1(1985,645.27) 2032.67,692.94 J3.3@2095.14,692.94
EXC_N: C14.1 Q2.2 R38.2 | length 328
  Top Layer w15: R38.2@1345.76,1170.93 1365.4,1151.29 1365.4,1102.15 ; Q2.2@1365.4,1018.08 1365.4,1102.15 ; C14.1@1476.23,1021.77 1476.23,1060.76 1434.84,1102.15 1365.4,1102.15
EXC_P: C10.1 R30.1 R32.2 | length 112.5
  Top Layer w15: R32.2@1292.22,899.01 1346.29,899.01 R30.1@1348.22,900.93 1402.64,900.93 C10.1@1403.57,900
GND: C1.2 C2.2 C3.1 C4.2 C5.1 C6.1 C7.1 C8.1 C12.1 C13.1 C16.1 C17.2 C18.1 C19.2 C20.2 C22.2 C23.2 C24.2 D2.1 D2.4 D3.1 D3.4 D4.1 D4.4 D5.1 D5.4 J1.9 J1.11 J1.13 Q1.1 Q1.4 R8.1 R13.1 R14.1 R24.1 R36.1 R37.1 R38.1 R47.1 R51.1 U1.3 U2.11 U3.3 U3.5 U3.7 U3.8 U3.9 U4.3 U4.5 U4.7 U4.8 U4.9 U5.6 U5.14 U5.15 U6.2 | length 4690.4
  Top Layer w6: R37.1@964.2,1178.36 993.3,1149.26 993.3,1080.74 986.73,1074.17 v1(986.73,1070.11)
  Top Layer w12: v1(436.67,153.6) 478.82,153.6 Q1.1@480.45,155.22 480.45,174.73 490.12,184.41 505.71,184.41 531.63,210.32 Q1.4@531.63,230.02
  Top Layer w15: v3(135,1142.01) 200,1142.01 200,1204.11 ; v3(135,1205) 199.11,1205 200,1204.11 ; C2.2@200,1225.78 200,1204.11 ; v1(401.84,524.97) 401.84,514.97 425.38,491.42 R8.1@448.54,491.42 ; U1.3@476.79,704.89 564.08,704.89 C17.2@585,683.97 594,683.97 C3.1@650,627.97 650.72,627.25 v1(650.72,573.01) ; C16.1@553.84,1123.4 553.84,1028.33 552.64,1027.14 555.77,1024.01 556.76,1025 v1(622.94,1025) ; C8.1@566.35,808.1 629.36,808.1 v1(632.7,804.76) 632.7,822.93 666.83,857.06 C18.1@686.19,857.06 ; R14.1@600,140 603.7,143.7 607.4,140 v1(650,140) ; C18.1@686.19,858.08 873.77,858.08 905.68,826.17 U2.11@905.68,795.29 ; R13.1@906.57,388.67 R24.1@964.93,388.67 964.93,417.65 v1(1005,457.72) ; C13.1@1192.03,1005.04 1192.07,1005 1192.81,1005.74 1220.52,1005.74 v1(1243.11,1028.33) ; v1(1221,171.13) 1240.38,151.75 U3.9@1257.14,151.75 ; v1(1241.97,1133.65) 1252.47,1133.65 R38.1@1289.76,1170.93 ; U4.9@1256.57,539.54 1256.57,504.18 1283.31,477.44 v1(1283.31,458.36) 1257.14,432.2 U3.8@1257.14,364.35 U3.7@1307.14,364.35 ; v1(1256.57,812.32) U4.8@1256.57,752.14 U4.7@1306.57,752.14 1306.57,796.57 1320,810 1405,810 ; C22.2@1387.8,1385 C20.2@1494.74,1385 1548.92,1385 v1(1563.92,1370) 1586.26,1347.66 1632.31,1347.66 1641.97,1357.32 U6.2@1641.97,1385.87 ; U4.5@1406.57,752.14 1406.57,808.43 1405,810 ; U3.5@1407.14,364.35 1407.14,323.86 1414,317 1507.14,317 U3.3@1507.14,364.35 ; U4.3@1506.57,752.14 1506.57,797.57 1494.14,810 1405,810 ; 1507.67,316.47 v1(1545.81,278.33) ; U5.14@1659.17,996.12 1732.01,996.12 v2(1732.01,1029.58) v5(1775.31,1072.89) ; C6.1@1675.88,280.28 1675.88,302.05 v1(1702.5,328.67) 1735.45,361.61 D4.1@1771.87,361.61 ; C7.1@1675.88,668.47 1674.07,670.28 v1(1674.07,724.19) 1682.3,732.42 D2.1@1772.04,732.42 ; v1@1723.42,532.42 D3.1@1771.87,532.42 ; C5.1@1730.84,1260.51 1737.76,1260.3 C5.1@1739.53,1260.24 ; C5.1@1737.81,1261.91 v1(1792.28,1262.17) ; D4.4@1846.67,310.43 1885.32,310.43 v1(1892.17,303.58) ; D3.4@1846.67,481.24 1853.91,474 v1(1886,474) ; R51.1@1853.57,1487.92 1870.16,1471.34 C23.2@2054.45,1471.34 2062.93,1471.34 2079.51,1487.92 2116.61,1487.92 2123.15,1494.46 v1(2124.09,1494.46) ; D2.4@1855.87,674.14 v1(1893,674.14) ; R47.1@1890,184.8 1890,203.19 1910.53,223.72 C19.2@1955,223.72 v1(1955,175) ; v1(1902.5,767.93) C12.1@1902.5,822 R36.1@1959.36,822 ; D5.1@2221.65,1431.64 2222.04,1432.03 v1(2222.04,1470) ; D5.4@2296.45,1380.46 2324.02,1380.46 v1(2334.48,1370)
  Top Layer w16: v2(1818.62,1116.2) 1826.5,1124.07 U5.6@1891.46,1124.07
  Bottom Layer w15: v2(1732.01,1029.58) v5(1775.31,1029.58) v2(1818.62,1029.58) ; v5(1775.31,1072.89) v2(1818.62,1072.89)
  Bottom Layer w16: v2(1732.01,1072.89) v5(1775.31,1072.89) ; v2(1732.01,1116.2) v5(1775.31,1116.2) v2(1818.62,1116.2)
  other v1: 1722.21,533.64
  other v2: 1732.01,986.28 1775.31,986.28 1818.62,986.28 1732.01,1159.5 1775.31,1159.5 1818.62,1159.5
